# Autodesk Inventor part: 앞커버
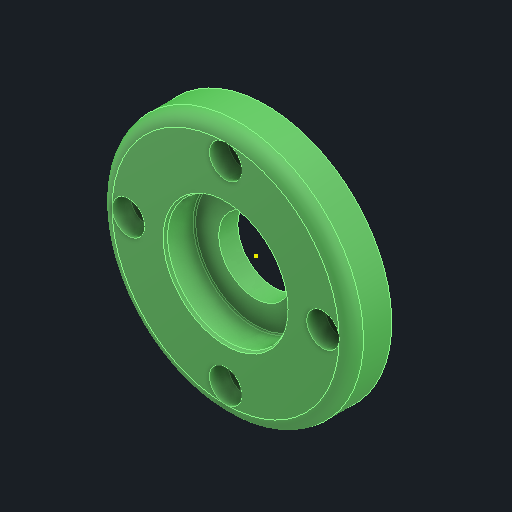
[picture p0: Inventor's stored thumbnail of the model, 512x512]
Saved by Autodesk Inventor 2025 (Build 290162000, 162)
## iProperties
Created: 2025-08
Part Number: 앞커버
Material: 알루미늄 6061
Document SubType Name: Modeling
Designer: infra012
Density: 2.71 g/cm^3
Appearance: 기본값
Author: jhkim
Sending System: Autodesk Inventor 2026
Preprocessor: ST-DEVELOPER v20.1
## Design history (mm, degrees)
sketch "스케치1"
  geometry: 1 further point
  constraints: 1 other
feature "솔리드1"
node "솔리드2"
